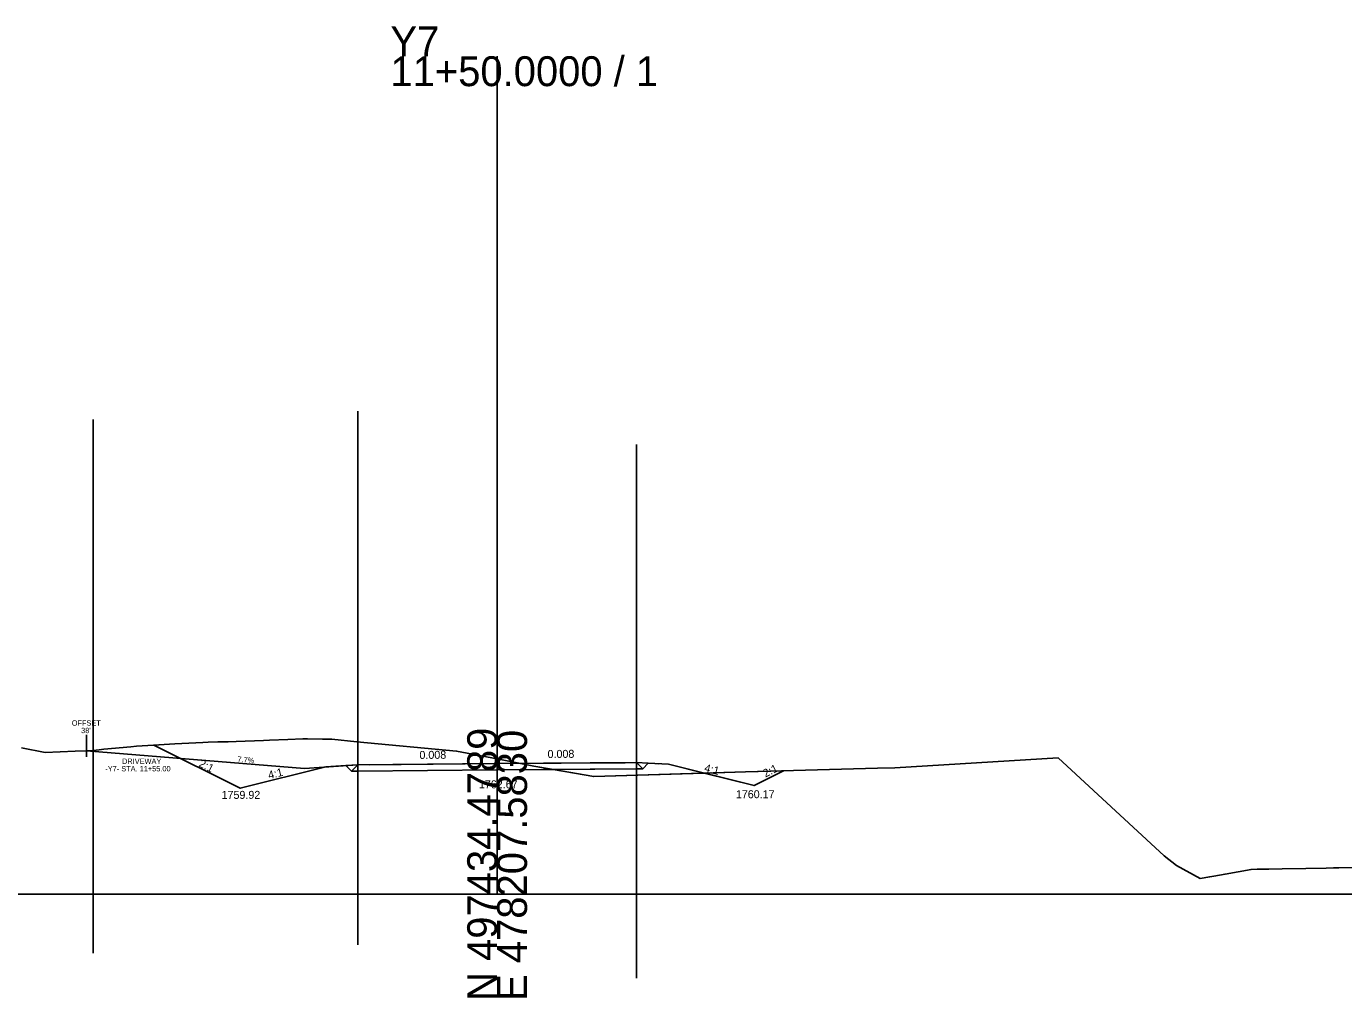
# Model space of a CAD drawing. Extents: x -26 to 403, y -10 to 4071.
# Drawn here: x 155.9 to 279.4, y 1490.3 to 1581.3 of the extents above; entities that cross this region are included whole.
import ezdxf

# ---------------------------------------------------------------- set-up
doc = ezdxf.new("R2010")
doc.units = 0
for name, color, linetype in [('Exist Cross Section Cell', 7, 'Continuous'), ('Exist XS Center Line Elevation Label', 7, 'Continuous'), ('Exist XS Ground Line', 7, 'Continuous'), ('Prop Road Sect_ Boring - Header (ID Tx)', 7, 'Continuous'), ('Prop Road Sect_ Boring - Material (Outline)', 7, 'Continuous'), ('Prop XS Ditch Slope Text', 7, 'Continuous'), ('Prop XS Ditch Standard Text', 7, 'Continuous'), ('Prop XS Dump Level', 7, 'Continuous'), ('Prop XS Earthwork Shape', 7, 'Continuous'), ('Prop XS EOT Tick Mark', 7, 'Continuous'), ('Prop XS Finish Grade', 7, 'Continuous'), ('Prop XS Finish Grade Earthwork', 7, 'Continuous'), ('Prop XS Finish Grade Pavement', 7, 'Continuous'), ('Prop XS Pvmt Edge Slope', 7, 'Continuous'), ('Prop XS SE Text', 7, 'Continuous'), ('Prop XS Side Slope Text', 7, 'Continuous'), ('Prop XS Subgrade Earthwork', 7, 'Continuous'), ('Scratch_Level_2', 7, 'Continuous'), ('Scratch_Level_5', 7, 'Continuous')]:
    doc.layers.add(name, color=color, linetype=linetype)

msp = doc.modelspace()

# ---------------------------------------------------------------- linework, layer by layer
at = {"layer": 'Exist Cross Section Cell'}
for p, q in [((200, 1500), (200, 1578.51)), ((0, 1500), (200, 1500)), ((200, 1500), (400, 1500))]:
    msp.add_line(p, q, dxfattribs=at)
at = {"layer": 'Exist XS Ground Line'}
msp.add_lwpolyline([(155.42, 1513.71), (157.64, 1513.27), (160.45, 1513.4), (161.47, 1513.44), (162.14, 1513.47), (162.7, 1513.54), (163.14, 1513.58), (165.66, 1513.82), (166.19, 1513.87), (167.79, 1513.97), (169.8, 1514.08), (172.42, 1514.22), (172.92, 1514.23), (173.83, 1514.26), (174.78, 1514.28), (175.55, 1514.3), (178.11, 1514.4), (178.67, 1514.42), (180.37, 1514.49), (181.79, 1514.55), (182.23, 1514.55), (183.64, 1514.53), (184.52, 1514.51), (186.84, 1514.28), (196.2, 1513.41), (200, 1512.67), (203.43, 1512.01), (209.06, 1511.02), (223.28, 1511.45), (235.67, 1511.81), (237.28, 1511.85), (252.58, 1512.77), (262.54, 1503.6), (263.67, 1502.68), (265.89, 1501.47), (266.8, 1501.63), (267.2, 1501.7), (268.24, 1501.89), (270.68, 1502.32), (271.26, 1502.33), (272.34, 1502.35), (273.59, 1502.37), (275.8, 1502.41), (277.73, 1502.45), (278.4, 1502.47), (278.91, 1502.48), (280.19, 1502.51)], dxfattribs=at)
at = {"layer": 'Prop Road Sect_ Boring - Header (ID Tx)'}
for points in [[(186.93, 1512.12), (185.83, 1512.05), (186.34, 1511.53)], [(213.65, 1511.75), (214.17, 1512.27), (213.07, 1512.33)]]:
    msp.add_lwpolyline(points, close=True, dxfattribs=at)
at = {"layer": 'Prop Road Sect_ Boring - Material (Outline)'}
for p, q in [((161.5, 1514.93), (161.5, 1512.86)), ((181.94, 1511.78), (161.5, 1513.44)), ((186.93, 1512.12), (181.94, 1511.78))]:
    msp.add_line(p, q, dxfattribs=at)
at = {"layer": 'Prop XS Dump Level'}
for p, q in [((187.99, 1512.13), (200, 1512.23)), ((200, 1512.23), (212.01, 1512.32))]:
    msp.add_line(p, q, dxfattribs=at)
at = {"layer": 'Prop XS Earthwork Shape'}
for points in [[(185.83, 1512.05), (183.93, 1511.92), (175.92, 1509.92), (167.81, 1513.97), (169.8, 1514.08), (172.42, 1514.22), (172.92, 1514.23), (173.83, 1514.26), (174.78, 1514.28), (175.55, 1514.3), (178.11, 1514.4), (178.67, 1514.42), (180.37, 1514.49), (181.79, 1514.55), (182.23, 1514.55), (183.64, 1514.53), (184.52, 1514.51), (186.84, 1514.28), (196.2, 1513.41), (200, 1512.67), (203.43, 1512.01), (205.29, 1511.69), (200, 1511.64), (186.93, 1511.54), (186.34, 1511.53)], [(213.07, 1511.75), (213.65, 1511.75), (214.17, 1512.27), (216.07, 1512.17), (219.42, 1511.34), (209.06, 1511.02), (205.29, 1511.69)], [(219.42, 1511.34), (224.08, 1510.17), (226.84, 1511.55), (223.28, 1511.45)]]:
    msp.add_lwpolyline(points, close=True, dxfattribs=at)
at = {"layer": 'Prop XS EOT Tick Mark'}
for p, q in [((186.93, 1512.12), (186.93, 1513.12)), ((213.07, 1512.33), (213.07, 1513.33))]:
    msp.add_line(p, q, dxfattribs=at)
at = {"layer": 'Prop XS Finish Grade'}
for p, q in [((186.93, 1512.12), (185.83, 1512.05)), ((213.07, 1512.33), (214.17, 1512.27))]:
    msp.add_line(p, q, dxfattribs=at)
at = {"layer": 'Prop XS Finish Grade Earthwork'}
for p, q in [((175.92, 1509.92), (167.81, 1513.97)), ((183.93, 1511.92), (175.92, 1509.92)), ((185.83, 1512.05), (183.93, 1511.92)), ((214.17, 1512.27), (216.07, 1512.17)), ((216.07, 1512.17), (224.08, 1510.17)), ((224.08, 1510.17), (226.84, 1511.55))]:
    msp.add_line(p, q, dxfattribs=at)
at = {"layer": 'Prop XS Finish Grade Pavement'}
for p, q in [((186.93, 1512.12), (200, 1512.23)), ((200, 1512.23), (213.07, 1512.33))]:
    msp.add_line(p, q, dxfattribs=at)
at = {"layer": 'Prop XS Pvmt Edge Slope'}
for p, q in [((186.93, 1512.12), (186.34, 1511.53)), ((213.07, 1512.33), (213.65, 1511.75))]:
    msp.add_line(p, q, dxfattribs=at)
at = {"layer": 'Prop XS Subgrade Earthwork'}
for p, q in [((186.34, 1511.53), (185.83, 1512.05)), ((186.93, 1511.54), (186.34, 1511.53)), ((200, 1511.64), (186.93, 1511.54)), ((213.07, 1511.75), (200, 1511.64)), ((213.07, 1511.75), (213.65, 1511.75)), ((213.65, 1511.75), (214.17, 1512.27))]:
    msp.add_line(p, q, dxfattribs=at)
at = {"layer": 'Scratch_Level_2'}
for p, q in [((186.93, 1545.27), (186.93, 1495.27)), ((162.14, 1544.47), (162.14, 1494.47)), ((213.07, 1542.14), (213.07, 1492.14))]:
    msp.add_line(p, q, dxfattribs=at)
at = {"layer": 'Scratch_Level_5'}
msp.add_lwpolyline([(155.42, 1513.71), (157.64, 1513.27), (160.45, 1513.4), (161.47, 1513.44), (162.14, 1513.47), (162.7, 1513.54), (163.14, 1513.58), (165.66, 1513.82), (166.19, 1513.87), (167.79, 1513.97), (169.8, 1514.08), (172.42, 1514.22), (172.92, 1514.23), (173.83, 1514.26), (174.78, 1514.28), (175.55, 1514.3), (178.11, 1514.4), (178.67, 1514.42), (180.37, 1514.49), (181.79, 1514.55), (182.23, 1514.55), (183.64, 1514.53), (184.52, 1514.51), (186.84, 1514.28), (196.2, 1513.41), (200, 1512.67), (203.43, 1512.01), (209.06, 1511.02), (223.28, 1511.45), (235.67, 1511.81), (237.28, 1511.85), (252.58, 1512.77), (262.54, 1503.6), (263.67, 1502.68), (265.89, 1501.47), (266.8, 1501.63), (267.2, 1501.7), (268.24, 1501.89), (270.68, 1502.32), (271.26, 1502.33), (272.34, 1502.35), (273.59, 1502.37), (275.8, 1502.41), (277.73, 1502.45), (278.4, 1502.47), (278.91, 1502.48), (280.19, 1502.51)], dxfattribs=at)

# ---------------------------------------------------------------- texts
at = {"layer": 'Exist Cross Section Cell'}
for s, p in [('Y7', (190, 1578.51)), ('11+50.0000 / 1', (190, 1575.71))]:
    msp.add_text(s, height=2.8, dxfattribs=at).set_placement(p)
for s, p in [('N 497434.4789', (200, 1490)), ('E 478207.5830', (202.8, 1490))]:
    msp.add_text(s, height=2.8, rotation=90, dxfattribs=at).set_placement(p)
at = {"layer": 'Exist XS Center Line Elevation Label'}
msp.add_text('1762.67', height=0.75, dxfattribs=at).set_placement((198.29, 1509.92))
at = {"layer": 'Prop Road Sect_ Boring - Material (Outline)'}
for s, p in [('OFFSET', (160.12, 1515.79)), ("38'", (161, 1515.09)), ('DRIVEWAY', (164.84, 1512.21)), ('-Y7- STA. 11+55.00', (163.27, 1511.51))]:
    msp.add_text(s, height=0.5, dxfattribs=at).set_placement(p)
msp.add_text('7.7%', height=0.5, rotation=354.2894, dxfattribs=at).set_placement((175.64, 1512.42))
at = {"layer": 'Prop XS Ditch Slope Text'}
for rotation, p in [(14.0255, (178.63, 1510.77)), (345.9745, (219.37, 1511.5))]:
    msp.add_text('4:1', height=0.75, rotation=rotation, dxfattribs=at).set_placement(p)
at = {"layer": 'Prop XS Ditch Standard Text'}
for s, p in [('1759.92', (174.17, 1508.93)), ('1760.17', (222.38, 1508.99))]:
    msp.add_text(s, height=0.75, dxfattribs=at).set_placement(p)
at = {"layer": 'Prop XS Dump Level'}
for p in [(184.98, 1511.89), (215.02, 1512.13)]:
    msp.add_text('Case1', height=0.04, dxfattribs=at).set_placement(p)
at = {"layer": 'Prop XS SE Text'}
for p in [(192.72, 1512.67), (204.73, 1512.76)]:
    msp.add_text('0.008', height=0.75, rotation=0.4584, dxfattribs=at).set_placement(p)
at = {"layer": 'Prop XS Side Slope Text'}
for rotation, p in [(333.4533, (171.97, 1512)), (26.5467, (225.15, 1510.92))]:
    msp.add_text('2:1', height=0.75, rotation=rotation, dxfattribs=at).set_placement(p)

doc.saveas('drawing.dxf')
